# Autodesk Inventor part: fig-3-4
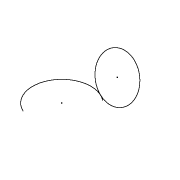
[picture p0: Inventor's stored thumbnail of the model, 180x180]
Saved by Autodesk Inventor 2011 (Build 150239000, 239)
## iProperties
Created: 2009-11
Part Number: fig-3-4
Document SubType Name: Modeling
Designer: Sham
Density: 1 g/cm^3
Author: Sham
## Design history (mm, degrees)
sketch "Sketch1"
  geometry: A1 r 10.623 centre (-1.113, -21.203) between (5.463, -12.861) and (-5.537, -30.861); 1 further point; 1 other entity
  constraints: 2 point on circle, 1 centre point, 4 other
